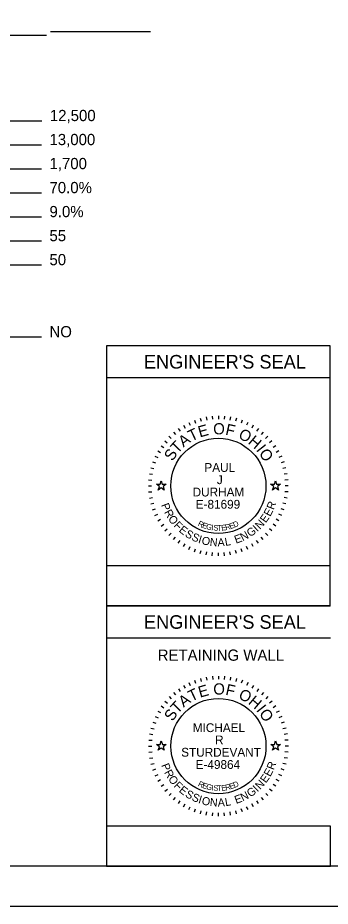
# Model space of a CAD drawing. Extents: x 0 to 45, y -99 to 22.
# Drawn here: x 7.34 to 11.25, y 0 to 11.1 of the extents above; entities that cross this region are included whole.
import ezdxf

# ---------------------------------------------------------------- set-up
doc = ezdxf.new("R2010")
doc.units = 0
for name, color, linetype in [('Default', 7, 'Continuous'), ('SH_Border', 7, 'Continuous'), ('SH_Cut_Line', 7, 'Continuous'), ('SH_Data', 7, 'Continuous'), ('SH_Text', 7, 'Continuous')]:
    doc.layers.add(name, color=color, linetype=linetype)

msp = doc.modelspace()

# ---------------------------------------------------------------- linework, layer by layer
at = {"layer": 'Default'}
for points in [[(9.074, 5.27), (9.121, 5.27), (9.135, 5.315), (9.149, 5.27), (9.196, 5.27), (9.158, 5.242), (9.173, 5.198), (9.135, 5.225), (9.097, 5.198), (9.112, 5.242)], [(10.504, 5.27), (10.551, 5.27), (10.565, 5.315), (10.579, 5.27), (10.626, 5.27), (10.588, 5.242), (10.603, 5.198), (10.565, 5.225), (10.527, 5.198), (10.542, 5.242)], [(9.075, 2.02), (9.122, 2.02), (9.136, 2.065), (9.151, 2.02), (9.198, 2.02), (9.16, 1.992), (9.174, 1.948), (9.136, 1.975), (9.098, 1.948), (9.113, 1.992)], [(10.505, 2.02), (10.552, 2.02), (10.566, 2.065), (10.581, 2.02), (10.628, 2.02), (10.59, 1.992), (10.604, 1.948), (10.566, 1.975), (10.528, 1.948), (10.543, 1.992)]]:
    msp.add_lwpolyline(points, close=True, dxfattribs=at)
at = {"layer": 'SH_Border'}
msp.add_lwpolyline([(1.5, 21.5), (33.5, 21.5), (33.5, 0.5), (1.5, 0.5)], close=True, dxfattribs=at)
at = {"layer": 'SH_Cut_Line'}
for p, q in [((7.7, 10.877), (3.347, 10.877)), ((9, 10.922), (7.75, 10.922)), ((7.642, 9.806), (3.871, 9.806)), ((7.637, 9.506), (4.189, 9.506)), ((7.637, 9.206), (4.872, 9.206)), ((7.637, 8.906), (4.604, 8.906)), ((7.637, 8.606), (4.189, 8.606)), ((7.637, 8.306), (3.346, 8.306)), ((7.637, 8.006), (3.242, 8.006)), ((7.637, 7.106), (3.267, 7.106)), ((11.25, 7), (8.45, 7)), ((8.45, 7), (8.45, 3.75)), ((11.25, 3.75), (11.25, 7)), ((11.25, 6.6), (8.45, 6.6)), ((9.698, 6.112), (9.705, 6.072)), ((9.774, 6.122), (9.777, 6.082)), ((9.85, 6.125), (9.85, 6.085)), ((9.926, 6.122), (9.923, 6.082)), ((10.002, 6.112), (9.995, 6.072)), ((9.413, 6.008), (9.433, 5.973)), ((9.48, 6.043), (9.497, 6.007)), ((9.551, 6.072), (9.564, 6.035)), ((9.624, 6.095), (9.634, 6.057)), ((10.076, 6.095), (10.066, 6.057)), ((10.149, 6.072), (10.136, 6.035)), ((10.22, 6.043), (10.203, 6.007)), ((10.287, 6.008), (10.267, 5.973)), ((9.288, 5.92), (9.313, 5.89)), ((9.348, 5.967), (9.371, 5.934)), ((10.352, 5.967), (10.329, 5.934)), ((10.412, 5.92), (10.387, 5.89)), ((9.18, 5.812), (9.21, 5.787)), ((9.231, 5.869), (9.26, 5.84)), ((10.469, 5.869), (10.44, 5.84)), ((10.52, 5.812), (10.49, 5.787)), ((9.092, 5.688), (9.127, 5.668)), ((9.133, 5.752), (9.166, 5.729)), ((10.567, 5.752), (10.534, 5.729)), ((10.608, 5.688), (10.573, 5.668)), ((9.028, 5.549), (9.065, 5.536)), ((9.057, 5.62), (9.093, 5.603)), ((10.643, 5.62), (10.607, 5.603)), ((10.672, 5.549), (10.635, 5.536)), ((9.005, 5.476), (9.043, 5.466)), ((10.695, 5.476), (10.657, 5.466)), ((8.988, 5.402), (9.028, 5.395)), ((10.712, 5.402), (10.672, 5.395)), ((8.975, 5.25), (9.015, 5.25)), ((8.978, 5.326), (9.018, 5.323)), ((10.722, 5.326), (10.682, 5.323)), ((10.725, 5.25), (10.685, 5.25)), ((8.978, 5.174), (9.018, 5.177)), ((8.988, 5.098), (9.028, 5.105)), ((10.712, 5.098), (10.672, 5.105)), ((10.722, 5.174), (10.682, 5.177)), ((9.005, 5.024), (9.043, 5.034)), ((10.695, 5.024), (10.657, 5.034)), ((9.028, 4.951), (9.065, 4.964)), ((9.057, 4.88), (9.093, 4.897)), ((10.643, 4.88), (10.607, 4.897)), ((10.672, 4.951), (10.635, 4.964)), ((9.092, 4.813), (9.127, 4.833)), ((10.608, 4.813), (10.573, 4.833)), ((9.133, 4.748), (9.166, 4.771)), ((9.18, 4.688), (9.21, 4.713)), ((10.52, 4.688), (10.49, 4.713)), ((10.567, 4.748), (10.534, 4.771)), ((9.231, 4.631), (9.26, 4.66)), ((9.288, 4.58), (9.313, 4.61)), ((9.348, 4.533), (9.371, 4.566)), ((10.352, 4.533), (10.329, 4.566)), ((10.412, 4.58), (10.387, 4.61)), ((10.469, 4.631), (10.44, 4.66)), ((9.413, 4.492), (9.433, 4.527)), ((9.48, 4.457), (9.497, 4.493)), ((9.551, 4.428), (9.564, 4.465)), ((9.624, 4.405), (9.634, 4.443)), ((10.076, 4.405), (10.066, 4.443)), ((10.149, 4.428), (10.136, 4.465)), ((10.22, 4.457), (10.203, 4.493)), ((10.287, 4.492), (10.267, 4.527)), ((9.698, 4.388), (9.705, 4.428)), ((9.774, 4.378), (9.777, 4.418)), ((9.85, 4.375), (9.85, 4.415)), ((9.926, 4.378), (9.923, 4.418)), ((10.002, 4.388), (9.995, 4.428)), ((11.25, 3.75), (8.45, 3.75)), ((11.251, 3.75), (8.451, 3.75)), ((8.451, 3.75), (8.451, 0.5)), ((11.251, 3.35), (8.451, 3.35)), ((9.482, 2.793), (9.499, 2.757)), ((9.552, 2.822), (9.566, 2.785)), ((9.625, 2.845), (9.635, 2.807)), ((9.699, 2.862), (9.706, 2.822)), ((9.775, 2.872), (9.779, 2.832)), ((9.851, 2.875), (9.851, 2.835)), ((9.928, 2.872), (9.924, 2.832)), ((10.003, 2.862), (9.996, 2.822)), ((10.078, 2.845), (10.068, 2.807)), ((10.151, 2.822), (10.137, 2.785)), ((10.221, 2.793), (10.204, 2.757)), ((9.289, 2.67), (9.315, 2.64)), ((9.35, 2.717), (9.372, 2.684)), ((9.414, 2.758), (9.434, 2.723)), ((10.289, 2.758), (10.269, 2.723)), ((10.353, 2.717), (10.33, 2.684)), ((10.414, 2.67), (10.388, 2.64)), ((9.181, 2.562), (9.212, 2.537)), ((9.233, 2.619), (9.261, 2.59)), ((10.47, 2.619), (10.442, 2.59)), ((10.522, 2.562), (10.491, 2.537)), ((9.135, 2.502), (9.167, 2.479)), ((10.568, 2.502), (10.535, 2.479)), ((9.058, 2.37), (9.095, 2.353)), ((9.094, 2.438), (9.128, 2.418)), ((10.609, 2.438), (10.575, 2.418)), ((10.644, 2.37), (10.608, 2.353)), ((9.006, 2.226), (9.045, 2.216)), ((9.029, 2.299), (9.067, 2.286)), ((10.674, 2.299), (10.636, 2.286)), ((10.697, 2.226), (10.658, 2.216)), ((8.99, 2.152), (9.029, 2.145)), ((10.713, 2.152), (10.674, 2.145)), ((8.976, 2), (9.016, 2)), ((8.98, 2.076), (9.02, 2.073)), ((10.723, 2.076), (10.683, 2.073)), ((10.726, 2), (10.686, 2)), ((8.98, 1.924), (9.02, 1.927)), ((10.723, 1.924), (10.683, 1.927)), ((8.99, 1.848), (9.029, 1.855)), ((9.006, 1.774), (9.045, 1.784)), ((10.697, 1.774), (10.658, 1.784)), ((10.713, 1.848), (10.674, 1.855)), ((9.029, 1.701), (9.067, 1.714)), ((10.674, 1.701), (10.636, 1.714)), ((9.058, 1.63), (9.095, 1.647)), ((9.094, 1.563), (9.128, 1.583)), ((10.609, 1.563), (10.575, 1.583)), ((10.644, 1.63), (10.608, 1.647)), ((9.135, 1.498), (9.167, 1.521)), ((9.181, 1.438), (9.212, 1.463)), ((10.522, 1.438), (10.491, 1.463)), ((10.568, 1.498), (10.535, 1.521)), ((9.233, 1.381), (9.261, 1.41)), ((9.289, 1.33), (9.315, 1.36)), ((10.414, 1.33), (10.388, 1.36)), ((10.47, 1.381), (10.442, 1.41)), ((9.35, 1.283), (9.372, 1.316)), ((9.414, 1.242), (9.434, 1.277)), ((9.482, 1.207), (9.499, 1.243)), ((10.221, 1.207), (10.204, 1.243)), ((10.289, 1.242), (10.269, 1.277)), ((10.353, 1.283), (10.33, 1.316)), ((9.552, 1.178), (9.566, 1.215)), ((9.625, 1.155), (9.635, 1.193)), ((9.699, 1.138), (9.706, 1.178)), ((9.775, 1.128), (9.779, 1.168)), ((9.851, 1.125), (9.851, 1.165)), ((9.928, 1.128), (9.924, 1.168)), ((10.003, 1.138), (9.996, 1.178)), ((10.078, 1.155), (10.068, 1.193)), ((10.151, 1.178), (10.137, 1.215)), ((11.251, 0.5), (8.451, 0.5))]:
    msp.add_line(p, q, dxfattribs=at)
for points in [[(11.25, 3.75), (11.25, 4.25), (8.45, 4.25), (8.45, 3.75)], [(11.251, 0.5), (11.251, 1), (8.451, 1), (8.451, 0.5)]]:
    msp.add_lwpolyline(points, close=True, dxfattribs=at)
for centre in [(9.85, 5.25), (9.851, 2)]:
    msp.add_circle(centre, 0.595, dxfattribs=at)
at = {"layer": 'SH_Data'}
msp.add_lwpolyline([(0, 0), (34, 0), (34, 22), (0, 22)], close=True, dxfattribs=at)

# ---------------------------------------------------------------- texts
at = {"layer": 'SH_Cut_Line'}
for s, height, p in [("ENGINEER'S SEAL", 0.17, (8.918, 6.715)), ('PAUL', 0.11, (9.675, 5.425)), ('J', 0.11, (9.831, 5.272)), ('DURHAM', 0.11, (9.528, 5.118)), ('E-81699', 0.11, (9.567, 4.965)), ("ENGINEER'S SEAL", 0.17, (8.919, 3.465)), ('RETAINING WALL', 0.14, (9.091, 3.066)), ('MICHAEL', 0.11, (9.53, 2.175)), ('R', 0.11, (9.809, 2.022)), ('STURDEVANT', 0.11, (9.385, 1.868)), ('E-49864', 0.11, (9.566, 1.715))]:
    msp.add_text(s, height=height, dxfattribs=at).set_placement(p)
for s, height, rotation, p in [('E', 0.14, 15.7571, (9.618, 5.854)), ('O', 0.14, 359.7812, (9.785, 5.894)), ('F', 0.14, 347.4362, (9.931, 5.892)), ('A', 0.14, 36.4747, (9.413, 5.728)), ('T', 0.14, 25.7167, (9.512, 5.802)), ('O', 0.14, 332.2586, (10.09, 5.852)), ('H', 0.14, 319.9136, (10.213, 5.786)), ('T', 0.14, 46.4344, (9.338, 5.646)), ('I', 0.14, 308.367, (10.316, 5.698)), ('S', 0.14, 57.1924, (9.278, 5.551)), ('O', 0.14, 303.1491, (10.352, 5.659)), ('P', 0.1, 291.494, (9.132, 5.012)), ('R', 0.1, 69.2322, (10.542, 4.945)), ('R', 0.1, 298.7311, (9.169, 4.922)), ('E', 0.1, 54.758, (10.443, 4.781)), ('E', 0.1, 61.9951, (10.498, 4.86)), ('O', 0.1, 306.4666, (9.215, 4.838)), ('F', 0.1, 314.7068, (9.284, 4.748)), ('R', 0.07, 334.487, (9.587, 4.755)), ('E', 0.07, 341.04, (9.641, 4.73)), ('G', 0.07, 347.4752, (9.691, 4.712)), ('R', 0.07, 11.9184, (9.942, 4.697)), ('E', 0.07, 17.6836, (10, 4.71)), ('D', 0.07, 23.3052, (10.051, 4.727)), ('N', 0.1, 47.0224, (10.37, 4.701)), ('E', 0.1, 321.4393, (9.348, 4.685)), ('S', 0.1, 328.6764, (9.424, 4.625)), ('I', 0.07, 353.7858, (9.759, 4.697)), ('S', 0.07, 356.8926, (9.786, 4.693)), ('T', 0.07, 3.0061, (9.836, 4.689)), ('E', 0.07, 6.0117, (9.889, 4.691)), ('N', 0.1, 27.3113, (10.154, 4.558)), ('G', 0.1, 35.0469, (10.248, 4.607)), ('I', 0.1, 43.287, (10.337, 4.671)), ('S', 0.1, 335.9134, (9.506, 4.577)), ('I', 0.1, 343.1505, (9.591, 4.54)), ('O', 0.1, 346.8859, (9.634, 4.525)), ('N', 0.1, 355.1261, (9.739, 4.502)), ('A', 0.1, 2.8617, (9.842, 4.494)), ('L', 0.1, 10.0987, (9.939, 4.499)), ('E', 0.1, 20.0742, (10.071, 4.527)), ('O', 0.14, 359.7812, (9.786, 2.644)), ('F', 0.14, 347.4362, (9.932, 2.642)), ('T', 0.14, 25.7167, (9.513, 2.552)), ('E', 0.14, 15.7571, (9.62, 2.604)), ('O', 0.14, 332.2586, (10.091, 2.602)), ('T', 0.14, 46.4344, (9.34, 2.396)), ('A', 0.14, 36.4747, (9.415, 2.478)), ('H', 0.14, 319.9136, (10.215, 2.536)), ('S', 0.14, 57.1924, (9.279, 2.301)), ('I', 0.14, 308.367, (10.318, 2.448)), ('O', 0.14, 303.1491, (10.354, 2.409)), ('P', 0.1, 291.494, (9.134, 1.762)), ('R', 0.1, 69.2322, (10.543, 1.695)), ('R', 0.1, 298.7311, (9.17, 1.672)), ('E', 0.1, 61.9951, (10.499, 1.61)), ('O', 0.1, 306.4666, (9.217, 1.588)), ('F', 0.1, 314.7068, (9.286, 1.498)), ('R', 0.07, 334.487, (9.589, 1.505)), ('D', 0.07, 23.3052, (10.052, 1.477)), ('N', 0.1, 47.0224, (10.372, 1.451)), ('E', 0.1, 54.758, (10.445, 1.531)), ('E', 0.1, 321.4393, (9.349, 1.435)), ('S', 0.1, 328.6764, (9.426, 1.375)), ('E', 0.07, 341.04, (9.642, 1.48)), ('G', 0.07, 347.4752, (9.693, 1.462)), ('I', 0.07, 353.7858, (9.76, 1.447)), ('S', 0.07, 356.8926, (9.787, 1.443)), ('T', 0.07, 3.0061, (9.837, 1.439)), ('E', 0.07, 6.0117, (9.89, 1.441)), ('R', 0.07, 11.9184, (9.944, 1.447)), ('E', 0.07, 17.6836, (10.001, 1.46)), ('G', 0.1, 35.0469, (10.249, 1.357)), ('I', 0.1, 43.287, (10.338, 1.421)), ('S', 0.1, 335.9134, (9.508, 1.327)), ('I', 0.1, 343.1505, (9.592, 1.29)), ('O', 0.1, 346.8859, (9.635, 1.275)), ('N', 0.1, 355.1261, (9.74, 1.252)), ('A', 0.1, 2.8617, (9.844, 1.244)), ('L', 0.1, 10.0987, (9.941, 1.249)), ('E', 0.1, 20.0742, (10.073, 1.277)), ('N', 0.1, 27.3113, (10.156, 1.308))]:
    msp.add_text(s, height=height, rotation=rotation, dxfattribs=at).set_placement(p)
at = {"layer": 'SH_Text'}
for s, p in [('12,500', (7.742, 9.806)), ('13,000', (7.737, 9.506)), ('1,700 ', (7.737, 9.206)), ('70.0% ', (7.737, 8.906)), ('9.0%  ', (7.737, 8.606)), ('55    ', (7.737, 8.306)), ('50    ', (7.737, 8.006)), ('NO    ', (7.737, 7.106))]:
    msp.add_text(s, height=0.14, dxfattribs=at).set_placement(p)

doc.saveas('drawing.dxf')
